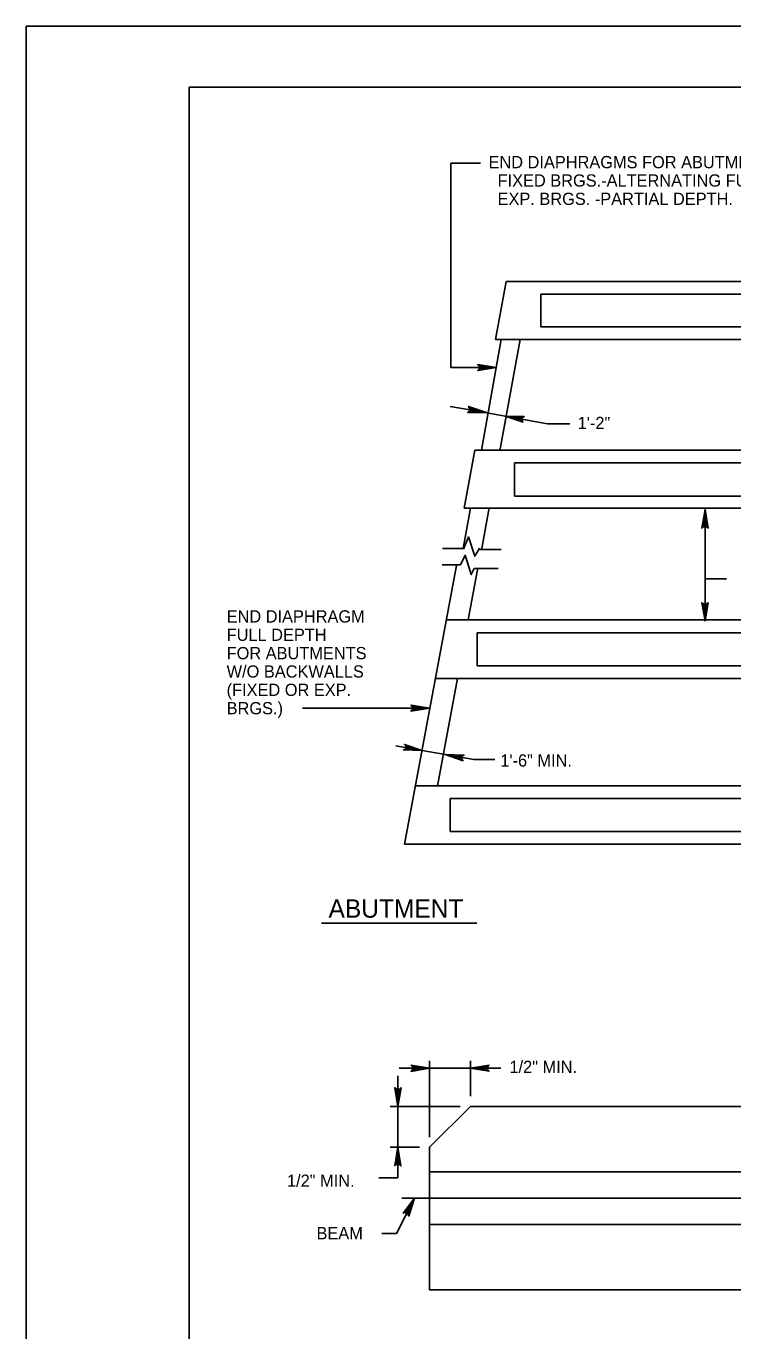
# Model space of a CAD drawing. Extents: x 639028 to 640031, y 298558 to 299746.
# Drawn here: x 639027.9 to 639201.3, y 299426.4 to 299746.3 of the extents above; entities that cross this region are included whole.
import ezdxf

# ---------------------------------------------------------------- set-up
doc = ezdxf.new("R2010")
doc.units = 0
doc.layers.add('1', color=7, linetype='Continuous')
doc.layers.add('PLT-BNDY', color=7, linetype='Continuous')

msp = doc.modelspace()

# ---------------------------------------------------------------- linework, layer by layer
at = {"layer": '1'}
for p, q in [((639067.87, 299167.33), (639067.87, 299731.33)), ((639067.87, 299731.33), (639853.87, 299731.33)), ((639139.33, 299712.73), (639132.08, 299712.73)), ((639132.08, 299662.6), (639132.08, 299712.73)), ((639145.7, 299683.73), (639143.08, 299669.48)), ((639145.7, 299683.73), (639424.83, 299683.73)), ((639154.2, 299680.6), (639277.2, 299680.6)), ((639154.2, 299680.6), (639154.2, 299672.6)), ((639277.2, 299672.6), (639154.2, 299672.6)), ((639144.45, 299669.48), (639139.58, 299642.35)), ((639143.08, 299669.48), (639422.2, 299669.48)), ((639149.08, 299669.48), (639144.08, 299642.23)), ((639143.2, 299662.6), (639132.08, 299662.6)), ((639131.95, 299653.1), (639140.83, 299651.6)), ((639140.95, 299651.48), (639145.45, 299650.73)), ((639145.45, 299650.73), (639155.83, 299648.85)), ((639161.32, 299648.85), (639155.83, 299648.85)), ((639137.95, 299642.35), (639135.33, 299628.1)), ((639137.95, 299642.35), (639417.2, 299642.35)), ((639147.7, 299639.23), (639268.58, 299639.23)), ((639147.7, 299639.23), (639147.7, 299631.1)), ((639268.58, 299631.1), (639147.7, 299631.1)), ((639136.95, 299628.1), (639135.08, 299618.23)), ((639135.33, 299628.1), (639414.58, 299628.1)), ((639141.45, 299628.23), (639139.58, 299617.85)), ((639194.45, 299600.48), (639194.45, 299627.85)), ((639130.08, 299618.23), (639135.08, 299618.23)), ((639139.08, 299617.98), (639144.45, 299617.98)), ((639133.45, 299614.1), (639120.7, 299545.73)), ((639129.95, 299614.23), (639134.45, 299614.23)), ((639138.7, 299613.48), (639136.33, 299600.73)), ((639137.83, 299613.35), (639143.7, 299613.35)), ((639199.7, 299610.85), (639194.58, 299610.85)), ((639130.95, 299600.73), (639409.58, 299600.73)), ((639138.58, 299597.6), (639264.13, 299597.6)), ((639138.58, 299597.6), (639138.58, 299589.48)), ((639264.13, 299589.48), (639138.58, 299589.48)), ((639128.2, 299586.35), (639406.95, 299586.35)), ((639133.7, 299586.35), (639128.83, 299560.1)), ((639126.83, 299579.1), (639095.7, 299579.1)), ((639118.58, 299569.85), (639125.08, 299568.73)), ((639125.08, 299568.73), (639130.7, 299567.73)), ((639130.7, 299567.73), (639137.7, 299566.48)), ((639142.92, 299566.48), (639137.7, 299566.48)), ((639123.45, 299560.1), (639401.95, 299560.1)), ((639131.95, 299556.98), (639256.94, 299556.98)), ((639131.95, 299556.98), (639131.95, 299548.85)), ((639256.94, 299548.85), (639131.95, 299548.85)), ((639120.7, 299545.73), (639399.33, 299545.73)), ((639100.33, 299526.35), (639138.45, 299526.35)), ((639119.39, 299490.84), (639144.39, 299490.84)), ((639126.89, 299473.96), (639126.89, 299492.6)), ((639136.89, 299483.96), (639136.89, 299492.6)), ((639119.1, 299463.96), (639119.1, 299488.96)), ((639134.39, 299481.46), (639117.18, 299481.46)), ((639136.89, 299481.46), (639126.89, 299471.46)), ((639226.89, 299481.46), (639136.89, 299481.46)), ((639124.39, 299471.46), (639117.18, 299471.46)), ((639126.89, 299471.46), (639126.89, 299436.46)), ((639126.89, 299465.39), (639246.89, 299465.39)), ((639119.1, 299463.96), (639114.41, 299463.98)), ((639118.76, 299450.32), (639123.21, 299458.96)), ((639120.08, 299458.96), (639246.89, 299458.96)), ((639126.89, 299452.53), (639246.89, 299452.53)), ((639115.14, 299450.32), (639118.76, 299450.32)), ((639226.89, 299436.46), (639126.89, 299436.46))]:
    msp.add_line(p, q, dxfattribs=at)
for points in [[(639138.83, 299663.23), (639139.08, 299662.85), (639143.2, 299662.6), (639138.83, 299663.23), (639138.7, 299663.35), (639143.2, 299662.6), (639139.08, 299662.48), (639138.95, 299662.1), (639143.2, 299662.6), (639138.7, 299661.85), (639138.95, 299662.1)], [(639136.58, 299652.85), (639136.7, 299652.48), (639140.83, 299651.6), (639136.58, 299652.85), (639136.45, 299653.1), (639140.83, 299651.6), (639136.7, 299652.1), (639136.45, 299651.85), (639140.83, 299651.6), (639136.2, 299651.6), (639136.45, 299651.85)], [(639149.58, 299649.35), (639149.58, 299649.73), (639145.45, 299650.73), (639149.58, 299649.35), (639149.83, 299649.23), (639145.45, 299650.73), (639149.58, 299650.23), (639149.83, 299650.48), (639145.45, 299650.73), (639150.08, 299650.6), (639149.83, 299650.48)], [(639193.95, 299623.48), (639194.2, 299623.6), (639194.45, 299627.85), (639193.95, 299623.48), (639193.7, 299623.23), (639194.45, 299627.85), (639194.7, 299623.6), (639194.95, 299623.48), (639194.45, 299627.85), (639195.2, 299623.23), (639194.95, 299623.48)], [(639194.08, 299625.23), (639194.33, 299625.35), (639194.45, 299627.85), (639194.08, 299625.23), (639194.08, 299625.1), (639194.45, 299627.85), (639194.58, 299625.35), (639194.7, 299625.23), (639194.45, 299627.85), (639194.83, 299625.1), (639194.7, 299625.23)], [(639135.2, 299618.1), (639136.45, 299621.1), (639137.95, 299616.35), (639139.08, 299618.35)], [(639134.45, 299614.23), (639135.58, 299616.6), (639137.08, 299611.85), (639137.83, 299613.35)], [(639194.95, 299604.73), (639194.7, 299604.6), (639194.45, 299600.48), (639194.95, 299604.73), (639195.2, 299604.98), (639194.45, 299600.48), (639194.2, 299604.6), (639193.95, 299604.73), (639194.45, 299600.48), (639193.7, 299604.98), (639193.95, 299604.73)], [(639194.83, 299603.1), (639194.58, 299602.98), (639194.45, 299600.48), (639194.83, 299603.1), (639194.83, 299603.23), (639194.45, 299600.48), (639194.33, 299602.98), (639194.08, 299603.1), (639194.45, 299600.48), (639194.08, 299603.23), (639194.08, 299603.1)], [(639122.45, 299579.6), (639122.7, 299579.35), (639126.83, 299579.1), (639122.45, 299579.6), (639122.33, 299579.85), (639126.83, 299579.1), (639122.7, 299578.85), (639122.45, 299578.6), (639126.83, 299579.1), (639122.33, 299578.35), (639122.45, 299578.6)], [(639120.95, 299570.1), (639121.08, 299569.73), (639125.08, 299568.73), (639120.95, 299570.1), (639120.7, 299570.23), (639125.08, 299568.73), (639120.95, 299569.23), (639120.7, 299568.98), (639125.08, 299568.73), (639120.45, 299568.85), (639120.7, 299568.98)], [(639134.83, 299566.48), (639134.7, 299566.73), (639130.7, 299567.73), (639134.83, 299566.48), (639135.08, 299566.23), (639130.7, 299567.73), (639134.83, 299567.23), (639135.08, 299567.48), (639130.7, 299567.73), (639135.33, 299567.6), (639135.08, 299567.48)], [(639122.61, 299491.35), (639122.67, 299490.98), (639126.89, 299490.84), (639122.61, 299491.35), (639122.32, 299491.55), (639126.89, 299490.84), (639122.74, 299490.61), (639122.53, 299490.32), (639126.89, 299490.84), (639122.33, 299490.03), (639122.53, 299490.32)], [(639141.16, 299490.28), (639141.1, 299490.65), (639136.89, 299490.84), (639141.16, 299490.28), (639141.45, 299490.07), (639136.89, 299490.84), (639141.04, 299491.02), (639141.24, 299491.3), (639136.89, 299490.84), (639141.45, 299491.59), (639141.24, 299491.3)], [(639119.65, 299485.73), (639119.28, 299485.67), (639119.1, 299481.46), (639119.65, 299485.73), (639119.86, 299486.02), (639119.1, 299481.46), (639118.91, 299485.61), (639118.62, 299485.82), (639119.1, 299481.46), (639118.34, 299486.02), (639118.62, 299485.82)], [(639118.52, 299467.19), (639118.89, 299467.25), (639119.1, 299471.46), (639118.52, 299467.19), (639118.31, 299466.9), (639119.1, 299471.46), (639119.26, 299467.31), (639119.54, 299467.1), (639119.1, 299471.46), (639119.83, 299466.89), (639119.54, 299467.1)], [(639120.75, 299455.42), (639121.11, 299455.31), (639123.21, 299458.96), (639120.75, 299455.42), (639120.43, 299455.26), (639123.21, 299458.96), (639121.46, 299455.19), (639121.62, 299454.88), (639123.21, 299458.96), (639121.78, 299454.56), (639121.62, 299454.88)]]:
    msp.add_lwpolyline(points, dxfattribs=at)
at = {"layer": 'PLT-BNDY'}
msp.add_lwpolyline([(639027.87, 299746.33), (639868.87, 299746.33), (639868.87, 299152.33), (639027.87, 299152.33)], close=True, dxfattribs=at)

# ---------------------------------------------------------------- texts
at = {"layer": '1'}
for s, height, p in [('END DIAPHRAGMS FOR ABUTMENTS WITH BACKWALLS:', 3, (639141.33, 299711.48)), ('  FIXED BRGS.-ALTERNATING FULL AND PARTIAL DEPTH.', 3, (639141.33, 299706.98)), ('  EXP. BRGS. -PARTIAL DEPTH.', 3, (639141.33, 299702.48)), ('1\'-2"', 3, (639163.21, 299647.53)), ('END DIAPHRAGM', 3, (639077.08, 299600.1)), ('FULL DEPTH', 3, (639077.08, 299595.6)), ('FOR ABUTMENTS', 3, (639077.08, 299591.1)), ('W/O BACKWALLS', 3, (639077.08, 299586.6)), ('(FIXED OR EXP.', 3, (639077.08, 299582.1)), ('BRGS.)', 3, (639077.08, 299577.6)), ('1\'-6" MIN.', 3, (639144.23, 299564.78)), ('ABUTMENT ', 4.5, (639102.08, 299527.73)), ('1/2" MIN.', 3, (639146.47, 299489.66)), ('1/2" MIN.', 3, (639091.89, 299461.75)), ('  BEAM', 3, (639096.9, 299448.89))]:
    msp.add_text(s, height=height, dxfattribs=at).set_placement(p)

doc.saveas('drawing.dxf')
